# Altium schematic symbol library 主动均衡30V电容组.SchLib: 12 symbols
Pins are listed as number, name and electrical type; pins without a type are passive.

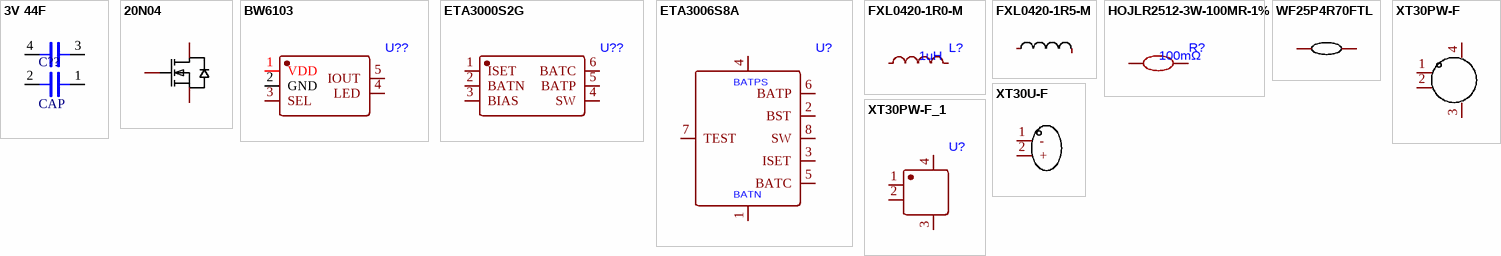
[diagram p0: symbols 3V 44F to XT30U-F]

## 3V 44F
designator C??, comment CAP
3V 40F 超级电容
footprint cap
pins: 1, 2, 3, 4

## 20N04
designator U??  (value not drawn)
40V 20A; Manufacturer: HL(富海微); Add into BOM: yes; Drain Source On Resistance (RDS(on)@Vgs,Id): 25mΩ; Gate Threshold Voltage (Vgs(th)@Id): 2.2V
footprint TO-252-2_L6.6-W6.1-P4.57-LS9.9-BR-CW
pins: 1 G, 2 D, 3 S

## BW6103
designator U??
3V 均压保护芯片
footprint TSOT-23-5_L2.9-W1.6-P0.95-LS2.8-BL
pins: 1 VDD, 2 GND, 3 SEL, 4 LED, 5 IOUT

## ETA3000S2G
designator U??
主动均衡芯片
footprint SOT-23-6_L2.9-W1.6-P0.95-LS2.8-BL-1
pins: 1 ISET, 2 BATN, 3 BIAS, 4 SW, 5 BATP, 6 BATC

## ETA3006S8A
designator U?
footprint SOIC-8_L5.0-W4.0-P1.27-LS6.0-TL
pins: 1 BATC, 2 BST, 3 ISET, 4 BATPS, 5 BATC, 6 BATP, 7 TEST, 8 SW

## FXL0420-1R0-M
designator L?, comment 1uH
footprint IND-SMD_L4.4-W4.2
pins: 1, 2

## FXL0420-1R5-M
designator L??  (value not drawn)
1.5uH; Manufacturer: cjiang(长江微电); Add into BOM: yes; Tolerance: ±20%; Rated Current: 5A; Saturation Current (Isat): 6A; DC Resistance (DCR): 46mΩ; Type: 一体成型电感
footprint IND-SMD_L4.4-W4.2
pins: 1, 2

## HOJLR2512-3W-100MR-1%
designator R?, comment 100mΩ
footprint RES-SMD_L6.4-W3.2-R2512
pins: 1, 2

## WF25P4R70FTL
designator R??  (value not drawn)
4.7Ω 2W; Manufacturer: Walsin(华新科); Add into BOM: yes; Tolerance: ±1%; Overload Voltage (Max): 300V; Temperature Coefficient: ±100ppm/℃
footprint R2512
pins: 1, 2

## XT30PW-F
designator U??  (value not drawn)
母头; Manufacturer: AMASS(艾迈斯); Add into BOM: yes; Brand: 艾迈斯
footprint CONN-TH_XT30PW-F-1
pins: 1, 2, 3, 4

## XT30PW-F_1
designator U?
footprint CONN-TH_XT30PW-F-1
pins: 1, 2, 3, 4

## XT30U-F
designator U??  (value not drawn)
Manufacturer: AMASS(艾迈斯); Add into BOM: yes; Brand: 艾迈斯; InterfaceType: 母头
footprint CONN-TH_XT30U-F
pins: 1 -, 2 +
